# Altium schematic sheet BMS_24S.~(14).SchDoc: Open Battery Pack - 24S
size A3; Date: 26/03/2019; Author: Morgane Vallée - Samuel Lesueur; Revision: 1.0; SheetNumber: 1; SheetTotal: 2
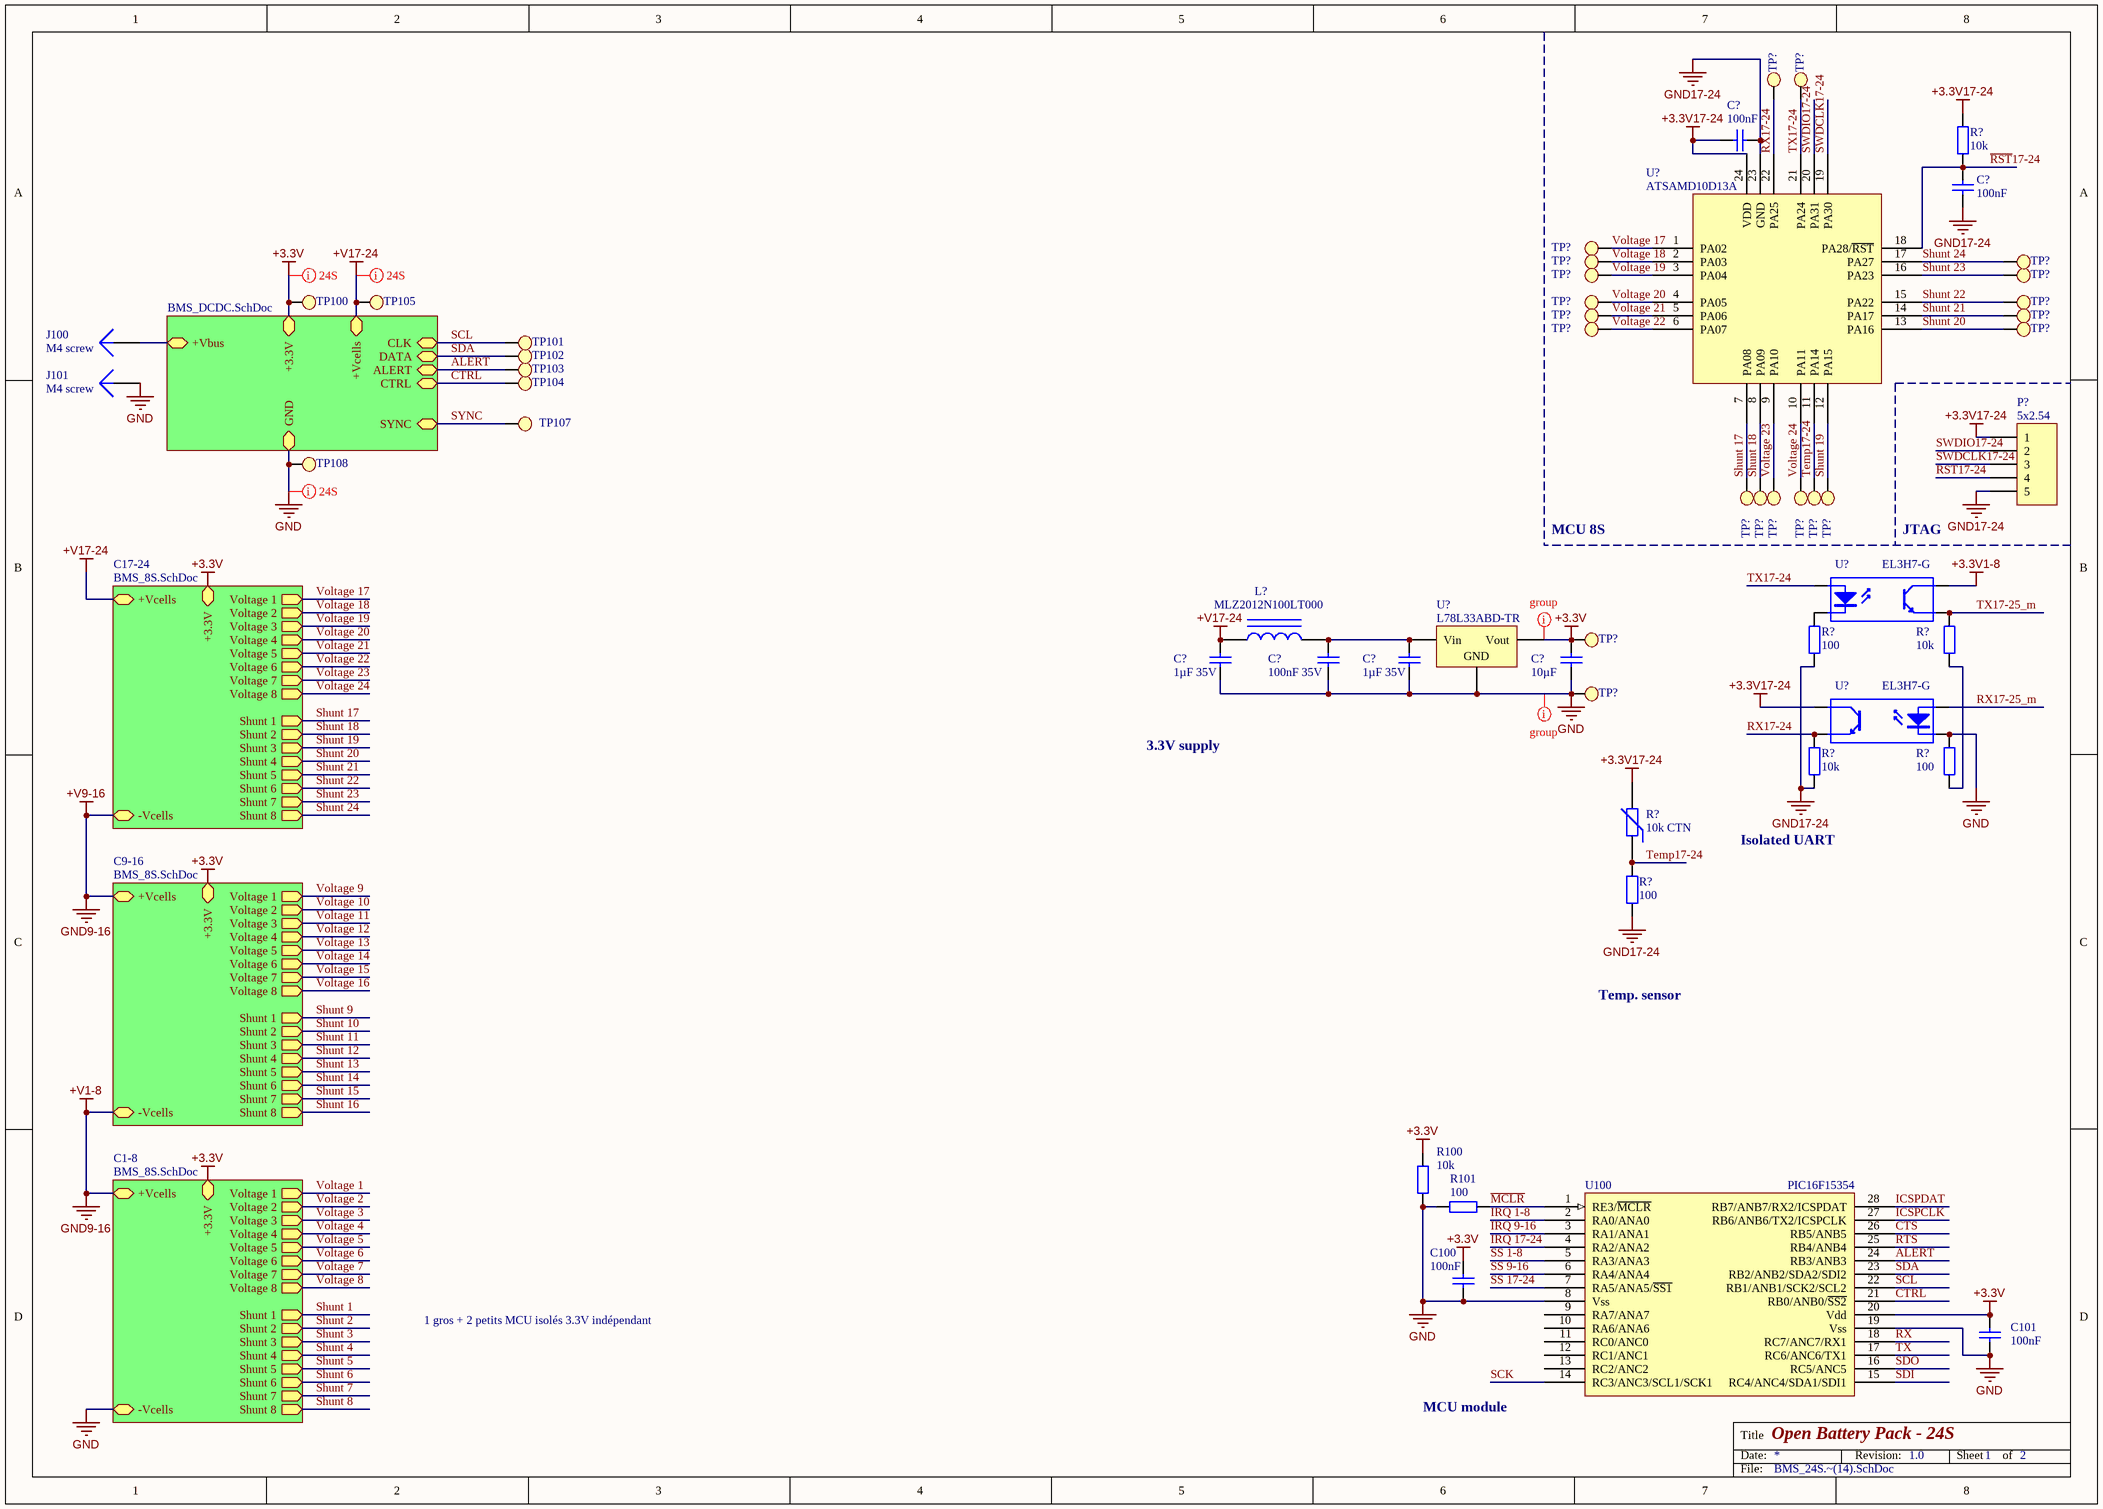
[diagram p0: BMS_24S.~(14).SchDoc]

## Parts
(Parts that share a designator on the sheet are numbered #1, #2 ... from top to bottom, then left to right.)
C100  100nF  [C0603]
C101  100nF  [C0603]
C?#1  100nF  [C0603]
C?#2  100nF  [C0603]
C?#3  1µF 35V  [C0805]
C?#4  100nF 35V  [C0603]
C?#5  1µF 35V  [C0805]
C?#6  10µF  [C0603]
J100  M4 screw  [HOLE_4]
J101  M4 screw  [HOLE_4]
L?  MLZ2012N100LT000  [FER 0805/2012]
P?  5x2.54  [HDR1X5]
R100  10k  [R0603]
R101  100  [R0603]
R?#1  10k  [R0603]
R?#2  10k  [R0603]
R?#3  100  [R0603]
R?#4  100  [R0603]
R?#5  10k  [R0603]
R?#6  10k CTN  [R0603]
R?#7  100  [R0603]
TP100  Test Point  [Test Point]  (value not drawn)
TP101  Test Point  [Test Point]  (value not drawn)
TP102  Test Point  [Test Point]  (value not drawn)
TP103  Test Point  [Test Point]  (value not drawn)
TP104  Test Point  [Test Point]  (value not drawn)
TP105  Test Point  [Test Point]  (value not drawn)
TP107  Test Point  [Test Point]  (value not drawn)
TP108  Test Point  [Test Point]  (value not drawn)
TP?#1  Test Point  [Test Point]  (value not drawn)
TP?#2  Test Point  [Test Point]  (value not drawn)
TP?#3  Test Point  [Test Point]  (value not drawn)
TP?#4  Test Point  [Test Point]  (value not drawn)
TP?#5  Test Point  [Test Point]  (value not drawn)
TP?#6  Test Point  [Test Point]  (value not drawn)
TP?#7  Test Point  [Test Point]  (value not drawn)
TP?#8  Test Point  [Test Point]  (value not drawn)
TP?#9  Test Point  [Test Point]  (value not drawn)
TP?#10  Test Point  [Test Point]  (value not drawn)
TP?#11  Test Point  [Test Point]  (value not drawn)
TP?#12  Test Point  [Test Point]  (value not drawn)
TP?#13  Test Point  [Test Point]  (value not drawn)
TP?#14  Test Point  [Test Point]  (value not drawn)
TP?#15  Test Point  [Test Point]  (value not drawn)
TP?#16  Test Point  [Test Point]  (value not drawn)
TP?#17  Test Point  [Test Point]  (value not drawn)
TP?#18  Test Point  [Test Point]  (value not drawn)
TP?#19  Test Point  [Test Point]  (value not drawn)
TP?#20  Test Point  [Test Point]  (value not drawn)
TP?#21  Test Point  [Test Point]  (value not drawn)
U100  PIC16F15354  [SSOP_28]
U?#1  ATSAMD10D13A  [SMSC QFN-24 4x4MM]
U?#2  EL3H7-G  [OPTO_EL3H7-G]
U?#3  L78L33ABD-TR  [ST SOIC-8N]
U?#4  EL3H7-G  [OPTO_EL3H7-G]

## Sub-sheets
C1-8 = BMS_8S.SchDoc: Voltage 6 (out), Shunt 2 (out), Shunt 7 (out), Shunt 6 (out), Voltage 3 (out), Voltage 5 (out), Shunt 8 (out), Voltage 8 (out), Voltage 7 (out), +3.3V, Voltage 2 (out), Shunt 4 (out), Shunt 3 (out), Shunt 5 (out), Voltage 4 (out), -Vcells, +Vcells, Shunt 1 (out), Voltage 1 (out)
C9-16 = BMS_8S.SchDoc: Voltage 6 (out), Shunt 2 (out), Shunt 7 (out), Shunt 6 (out), Voltage 3 (out), Voltage 5 (out), Shunt 8 (out), Voltage 8 (out), Voltage 7 (out), +3.3V, Voltage 2 (out), Shunt 4 (out), Shunt 3 (out), Shunt 5 (out), Voltage 4 (out), -Vcells, +Vcells, Shunt 1 (out), Voltage 1 (out)
C17-24 = BMS_8S.SchDoc: Voltage 6 (out), Shunt 2 (out), Shunt 7 (out), Shunt 6 (out), Voltage 3 (out), Voltage 5 (out), Shunt 8 (out), Voltage 8 (out), Voltage 7 (out), +3.3V, Voltage 2 (out), Shunt 4 (out), Shunt 3 (out), Shunt 5 (out), Voltage 4 (out), -Vcells, +Vcells, Shunt 1 (out), Voltage 1 (out)
? = BMS_DCDC.SchDoc: CTRL (bidir), SYNC (bidir), CLK (bidir), DATA (bidir), ALERT (bidir), GND, +3.3V, +Vbus, +Vcells

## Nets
+3.3V: C100.2 C101.2 C?#6.1 R100.2 TP100.1 TP?#20.1 U100.20(Vdd) U?#3.3(Vout) ; sheet /+3.3V, sheet C1-8/+3.3V, sheet C9-16/+3.3V, sheet C17-24/+3.3V
+3.3V1-8: U?#2.4(C)
+3.3V17-24: C?#1.2 P?.1 R?#1.2 R?#6.2 U?#1.24(VDD) U?#4.4(C)
+V1-8: sheet C1-8/+Vcells, sheet C9-16/-Vcells, sheet C9-16/+Vcells, sheet C17-24/-Vcells  [also labelled +V9-16, GND9-16]
+V17-24: C?#3.1 L?.1 TP105.1 ; sheet /+Vcells, sheet C17-24/+Vcells
GND: C100.1 C101.1 C?#3.2 C?#4.2 C?#5.2 C?#6.2 J101.1 R100.1 R101.2 R?#4.1 TP108.1 TP?#21.1 U100.8(Vss) U100.19(Vss) U?#3.2(GND) U?#4.2(K) ; sheet /GND, sheet C1-8/-Vcells
GND17-24: C?#1.1 C?#2.1 P?.5 R?#3.1 R?#5.1 R?#7.2 U?#1.23(GND)
ALERT: TP103.1 U100.24(RB3/ANB3) ; sheet /ALERT
CTRL: TP104.1 U100.21(RB0/ANB0/~{SS2}) ; sheet /CTRL
CTS: U100.26(RB5/ANB5)
ICSPCLK: U100.27(RB6/ANB6/TX2/ICSPCLK)
ICSPDAT: U100.28(RB7/ANB7/RX2/ICSPDAT)
IRQ 1-8: U100.2(RA0/ANA0)
IRQ 9-16: U100.3(RA1/ANA1)
IRQ 17-24: U100.4(RA2/ANA2)
~{MCLR}: R101.1 U100.1(RE3/~{MCLR})
~{RST}17-24: C?#2.2 P?.4 R?#1.1 U?#1.18(PA28/~{RST})
RTS: U100.25(RB4/ANB4)
RX: U100.18(RC7/ANC7/RX1)
RX17-24: R?#5.2 TP?#1.1 U?#1.22(PA25) U?#4.3(E)
RX17-25_m: U?#4.1(A)
~{SS} 1-8: U100.5(RA3/ANA3)
~{SS} 9-16: U100.6(RA4/ANA4)
~{SS} 17-24: U100.7(RA5/ANA5/~{SS1})
SCK: U100.14(RC3/ANC3/SCL1/SCK1)
SCL: TP101.1 U100.22(RB1/ANB1/SCK2/SCL2) ; sheet /CLK
SDA: TP102.1 U100.23(RB2/ANB2/SDA2/SDI2) ; sheet /DATA
SDI: U100.15(RC4/ANC4/SDA1/SDI1)
SDO: U100.16(RC5/ANC5)
Shunt 17: TP?#14.1 U?#1.7(PA08) ; sheet C17-24/Shunt 1
Shunt 18: TP?#15.1 U?#1.8(PA09) ; sheet C17-24/Shunt 2
Shunt 19: TP?#19.1 U?#1.12(PA15) ; sheet C17-24/Shunt 3
Shunt 20: TP?#13.1 U?#1.13(PA16) ; sheet C17-24/Shunt 4
Shunt 21: TP?#11.1 U?#1.14(PA17) ; sheet C17-24/Shunt 5
Shunt 22: TP?#9.1 U?#1.15(PA22) ; sheet C17-24/Shunt 6
Shunt 23: TP?#7.1 U?#1.16(PA23) ; sheet C17-24/Shunt 7
Shunt 24: TP?#5.1 U?#1.17(PA27) ; sheet C17-24/Shunt 8
SWDCLK17-24: P?.3 U?#1.19(PA30)
SWDIO17-24: P?.2 U?#1.20(PA31)
SYNC: TP107.1 ; sheet /SYNC
Temp17-24: R?#6.1 R?#7.1 TP?#18.1 U?#1.11(PA14)
TX: U100.17(RC6/ANC6/TX1)
TX17-24: TP?#2.1 U?#1.21(PA24) U?#2.1(A)
TX17-25_m: R?#2.1 U?#2.3(E)
Voltage 17: TP?#3.1 U?#1.1(PA02) ; sheet C17-24/Voltage 1
Voltage 18: TP?#4.1 U?#1.2(PA03) ; sheet C17-24/Voltage 2
Voltage 19: TP?#6.1 U?#1.3(PA04) ; sheet C17-24/Voltage 3
Voltage 20: TP?#8.1 U?#1.4(PA05) ; sheet C17-24/Voltage 4
Voltage 21: TP?#10.1 U?#1.5(PA06) ; sheet C17-24/Voltage 5
Voltage 22: TP?#12.1 U?#1.6(PA07) ; sheet C17-24/Voltage 6
Voltage 23: TP?#16.1 U?#1.9(PA10) ; sheet C17-24/Voltage 7
Voltage 24: TP?#17.1 U?#1.10(PA11) ; sheet C17-24/Voltage 8
NetC?#4_1: C?#4.1 C?#5.1 L?.2 U?#3.1(Vin)
NetJ100_1: J100.1 ; sheet /+Vbus
NetR?#2_2: R?#2.2 R?#4.2
NetR?#3_2: R?#3.2 U?#2.2(K)

Not connected (* = marked no-connect by the designer): U100 9(RA7/ANA7) 10(RA6/ANA6) 11(RC0/ANC0) 12(RC1/ANC1) 13(RC2/ANC2)

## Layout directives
net class 24S: +3.3V, +V17-24, GND
net class Group: +3.3V, GND

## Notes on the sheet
- MCU 8S
- (near U?#2) JTAG
- 3.3V supply
- Isolated UART
- Temp. sensor
- 1 gros + 2 petits MCU isolés 3.3V indépendant
- MCU module

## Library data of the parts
C100 C101 C?#1-C?#6 = Cap: Capacitor
J100 J101 = Plug
L? = Inductor Iron: Magnetic-Core Inductor
P? = Header 5: Header, 5-Pin
R100 R101 R?#1-R?#5 R?#7 = Res2: Resistor
R?#6 = Res Varistor: Varistor (Voltage-Sensitive Resistor)
U?#2 U?#4 = Optoisolator1: 4-Pin Phototransistor Optocoupler
U?#3 = Volt Reg: Voltage Regulator; pin to pad: 1>8 2>2+3+6+7 3>1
